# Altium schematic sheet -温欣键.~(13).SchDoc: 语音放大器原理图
size A4; Organization: 江门职业技术学院; Address1: 14电路设计1班; Address2: 温欣键; Address3: 学号：141806043; SheetNumber: 1; SheetTotal: 1
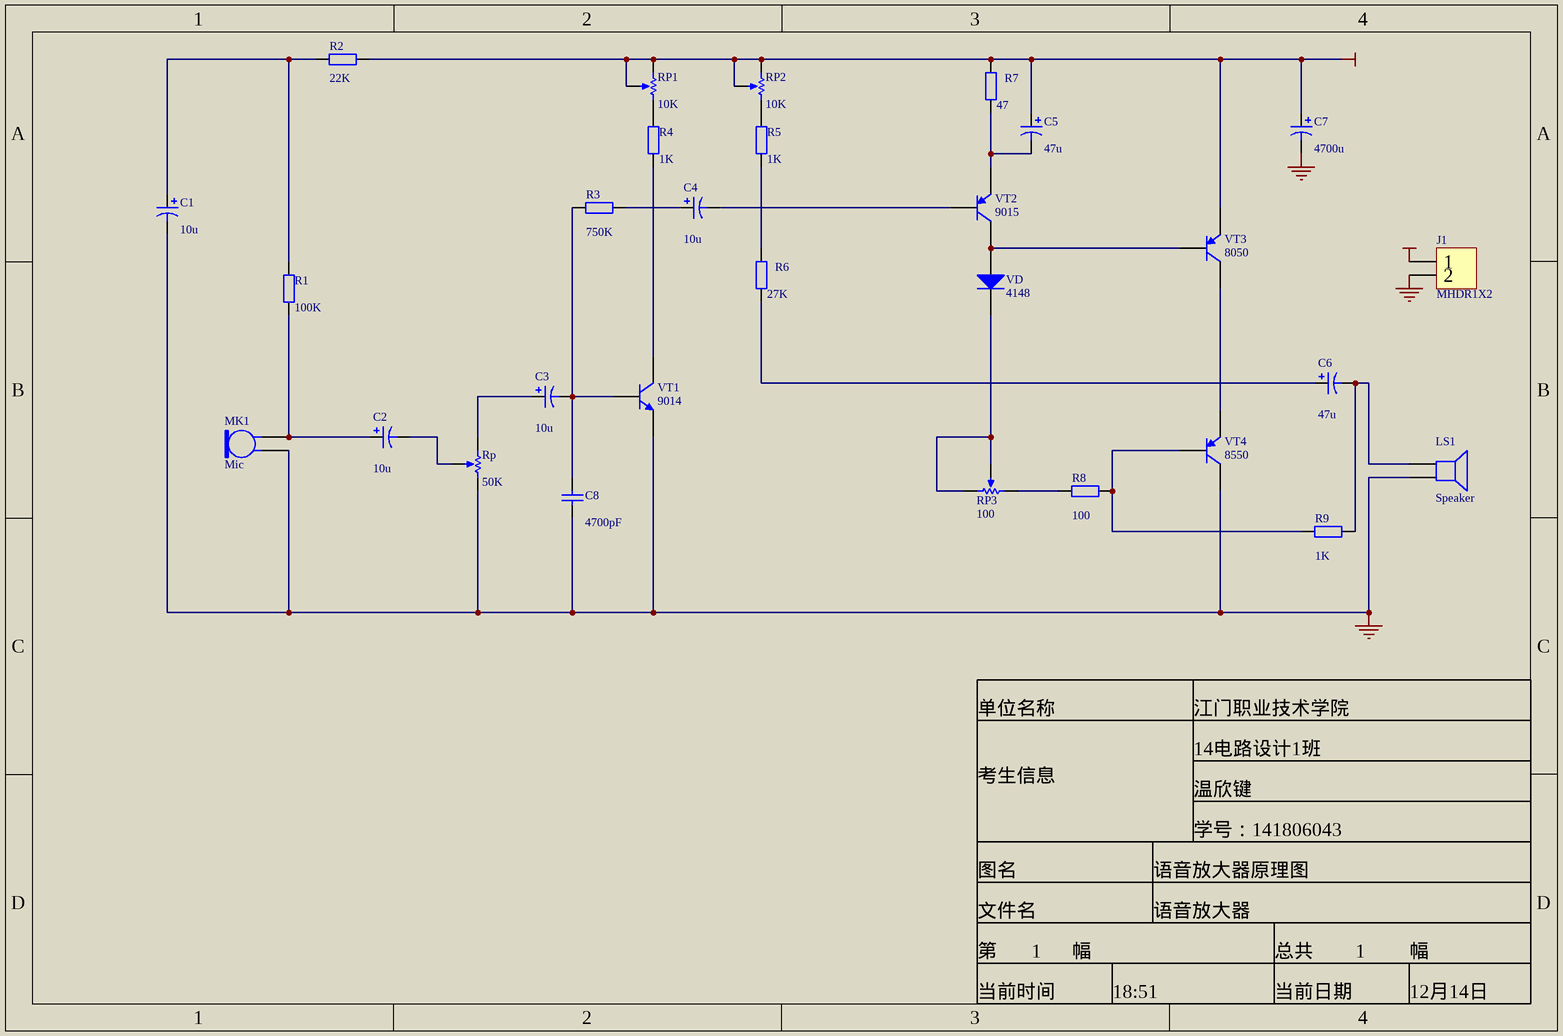
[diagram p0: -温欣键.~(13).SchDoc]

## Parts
C1  value 10u  [CAPPR7.5-16x35]  (hidden comment: Cap Pol1)
C2  value 10u  [CAPPR7.5-16x35]  (hidden comment: Cap Pol1)
C3  value 10u  [CAPPR7.5-16x35]  (hidden comment: Cap Pol1)
C4  value 10u  [CAPPR7.5-16x35]  (hidden comment: Cap Pol1)
C5  value 47u  [CAPPR7.5-16x35]  (hidden comment: Cap Pol1)
C6  value 47u  [CAPPR7.5-16x35]  (hidden comment: Cap Pol1)
C7  value 4700u  [CAPPR7.5-16x35]  (hidden comment: Cap Pol1)
C8  value 4700pF  [RAD-0.3]  (hidden comment: Cap)
J1  MHDR1X2  [HDR1X2]
LS1  Speaker  [PIN2]
MK1  Mic  [PIN2]
R1  value 100K  [AXIAL-0.4]  (hidden comment: Res2)
R2  value 22K  [AXIAL-0.4]  (hidden comment: Res2)
R3  value 750K  [AXIAL-0.4]  (hidden comment: Res2)
R4  value 1K  [AXIAL-0.4]  (hidden comment: Res2)
R5  value 1K  [AXIAL-0.4]  (hidden comment: Res2)
R6  value 27K  [AXIAL-0.4]  (hidden comment: Res2)
R7  47  [AXIAL-0.4]
R8  value 100  [AXIAL-0.4]  (hidden comment: Res2)
R9  value 1K  [AXIAL-0.4]  (hidden comment: Res2)
Rp  value 50K  [RM065]  (hidden comment: RPot)
RP1  value 10K  [RM065]  (hidden comment: RPot)
RP2  value 10K  [RM065]  (hidden comment: RPot)
RP3  100  [RM065]
VD  4148  [DO-35]
VT1  9014  [BCY-W3/E4]
VT2  9015  [BCY-W3/E4]
VT3  8050  [BCY-W3/E4]
VT4  8550  [BCY-W3/E4]

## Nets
GND: C1.2 C7.2 C8.1 J1.2 LS1.2 MK1.1 Rp.2(BOT) VT1.1(E) VT4.3(C)
VCC: C5.1 C7.1 J1.1 R2.1 R7.2 RP1.1(TOP) RP1.3(TAP) RP2.1(TOP) RP2.3(TAP) VT3.1(E)
NetC1_1: C1.1 R1.1 R2.2
NetC2_1: C2.1 MK1.2 R1.2
NetC2_2: C2.2 Rp.3(TAP)
NetC3_1: C3.1 Rp.1(TOP)
NetC3_2: C3.2 C8.2 R3.1 VT1.2(B)
NetC4_1: C4.1 R3.2
NetC4_2: C4.2 VT2.2(B)
NetC5_2: C5.2 R7.1 VT2.1(E)
NetC6_1: C6.1 R6.1
NetC6_2: C6.2 LS1.1 R9.1
NetR4_1: R4.1 VT1.3(C)
NetR4_2: R4.2 RP1.2(BOT)
NetR5_1: R5.1 RP2.2(BOT)
NetR5_2: R5.2 R6.2
NetR8_1: R8.1 RP3.1(TOP)
NetR8_2: R8.2 R9.2 VT4.2(B)
NetRP3_2: RP3.2(BOT) RP3.3(TAP) VD.2(K)
NetVD_1: VD.1(A) VT2.3(C) VT3.2(B)
NetVT3_3: VT3.3(C) VT4.1(E)

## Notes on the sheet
- 单位名称
- 考生信息
- 图名
- 文件名
- 第
- 幅
- 总共
- 当前时间
- 当前日期

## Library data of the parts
C1-C7 = Cap Pol1: Polarized Capacitor (Radial)
C8 = Cap: Capacitor
J1 = Header 2: Header, 2-Pin
LS1 = Speaker: Loudspeaker
MK1 = Mic2: Microphone
R1-R9 = Res2: Resistor
Rp RP1-RP3 = RPot: Potentiometer; Sim Note: Enter the Resistance value and the set point into parameter fields.; Set Position: 0.5
VD = 1N4148: High Conductance Fast Diode
VT1 = 2N3904: NPN General Purpose Amplifier
VT2-VT4 = 2N3906: PNP General Purpose Amplifier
